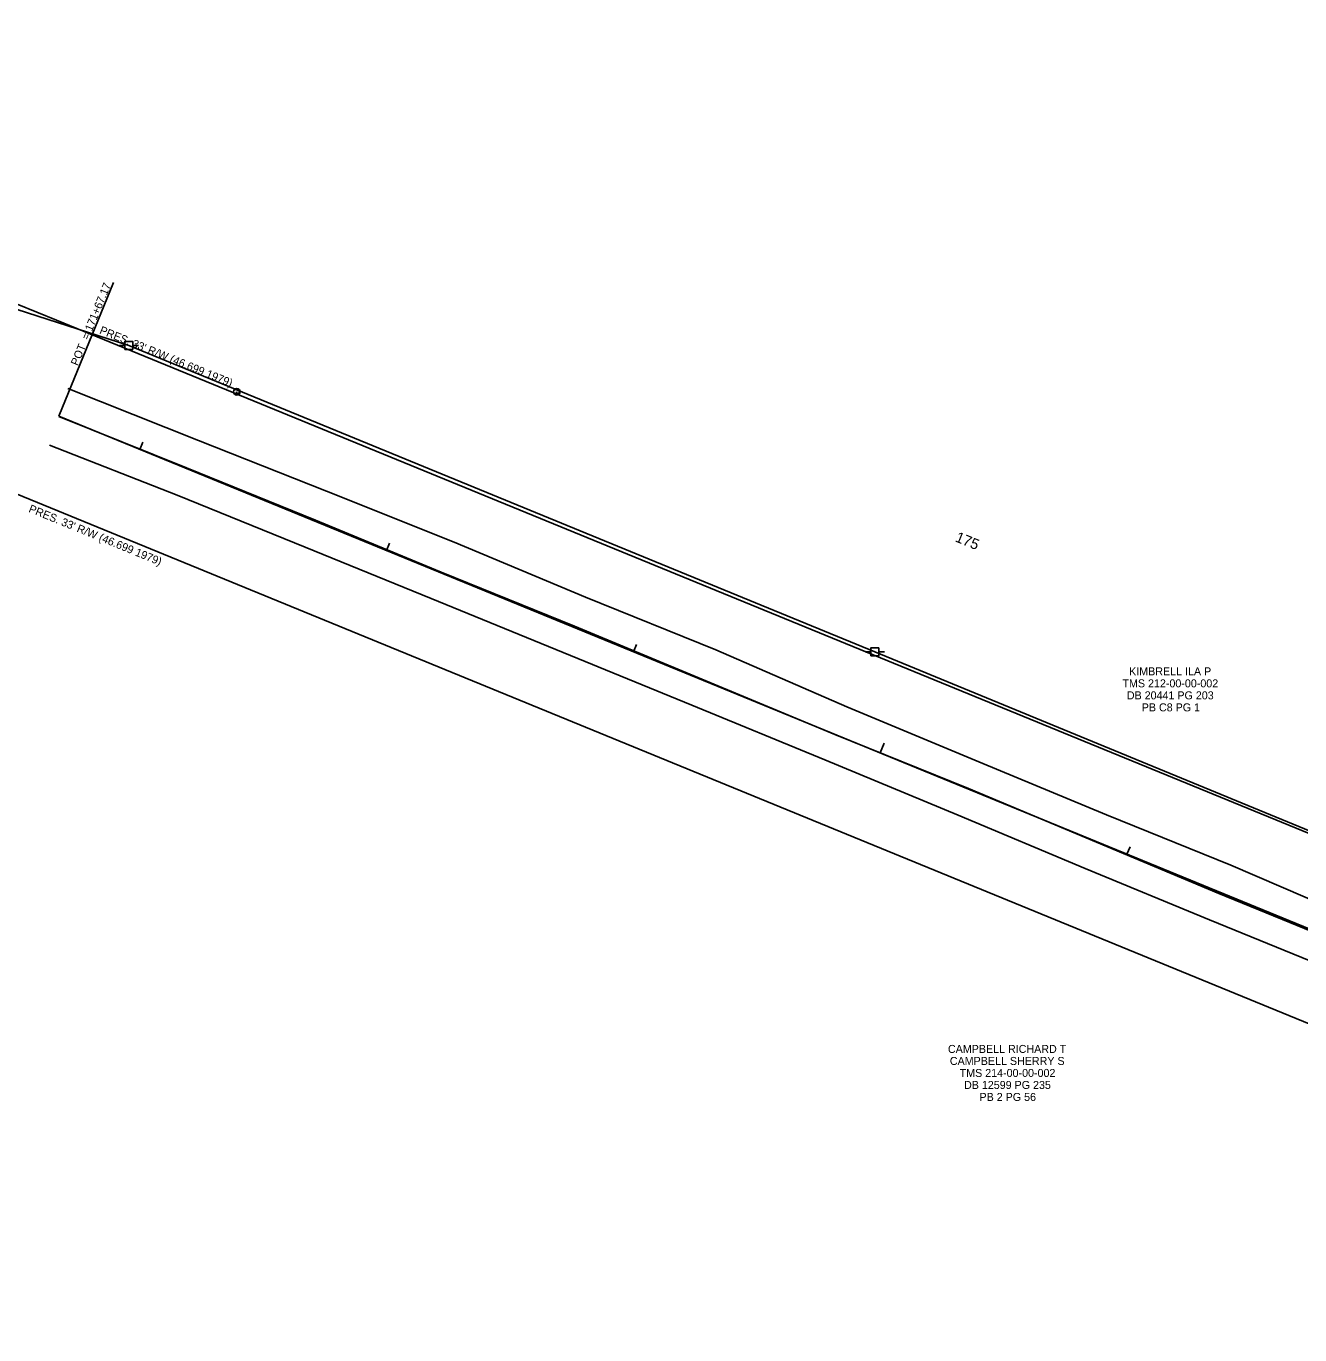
# Model space of a CAD drawing. Extents: x 1903662 to 1907233, y 1108998 to 1112872.
# Drawn here: x 1904852.9 to 1905330.5, y 1110014.7 to 1110505.3 of the extents above; entities that cross this region are included whole.
import ezdxf

# ---------------------------------------------------------------- set-up
doc = ezdxf.new("R2010")
doc.units = 0
for name, color, linetype in [('RD_DTM_BkLn1', 7, 'Continuous'), ('RD_EX_DV_TX_Prop', 7, 'Continuous'), ('RD_EX_Road', 7, 'Continuous'), ('RD_EX_RW', 7, 'Continuous'), ('RD_EX_RW_TX', 7, 'Continuous'), ('RD_EX_UT', 7, 'Continuous'), ('RD_HC_Cl', 7, 'Continuous'), ('RD_HC_Data', 7, 'Continuous'), ('RD_HC_Data_Tic', 7, 'Continuous'), ('RD_HC_TX_Sta20', 7, 'Continuous'), ('SV_UT_Electric_Lines', 7, 'Continuous')]:
    doc.layers.add(name, color=color, linetype=linetype)

msp = doc.modelspace()

# ---------------------------------------------------------------- linework, layer by layer
at = {"layer": 'RD_DTM_BkLn1'}
msp.add_lwpolyline([(1904865.19, 1110359), (1904913.1, 1110339.8), (1904961.42, 1110320.08), (1905008.53, 1110300.58), (1905058.58, 1110280.34), (1905106.3, 1110260.53), (1905156.09, 1110239.84), (1905206.21, 1110219.59), (1905254.3, 1110199.45), (1905300.11, 1110180.14), (1905347.21, 1110160.98), (1905395.33, 1110141.42), (1905443.75, 1110121.81), (1905492.46, 1110101.83), (1905520.15, 1110090.53), (1905547.72, 1110079.36), (1905575.52, 1110068.04), (1905603.32, 1110056.68), (1905630.91, 1110045.24), (1905658.56, 1110033.72), (1905686.41, 1110022.54)], dxfattribs=at)
at = {"layer": 'RD_EX_Road'}
for points in [[(1905496.35, 1110111.49), (1905446.77, 1110132.25), (1905399.76, 1110150.99), (1905351.42, 1110170.63), (1905304.67, 1110190.78), (1905258, 1110209.73), (1905210.14, 1110229.59), (1905160.61, 1110250.11), (1905111.53, 1110271.5), (1905062.64, 1110291.27), (1905013.42, 1110311.88), (1904965.6, 1110330.96), (1904917.58, 1110350.01), (1904868.56, 1110369.54)], [(1905488.55, 1110092.85), (1905440.52, 1110111.68), (1905391.25, 1110131.57), (1905343.49, 1110151.21), (1905296.63, 1110170.35), (1905249.95, 1110189.58), (1905202.45, 1110209.57), (1905152.37, 1110230.29), (1905102.47, 1110250.73), (1905054.27, 1110270.47), (1905004.76, 1110290.72), (1904957.54, 1110310), (1904909.51, 1110329.47), (1904861.73, 1110348.28)]]:
    msp.add_lwpolyline(points, dxfattribs=at)
at = {"layer": 'RD_EX_RW'}
for p, q in [((1904864.32, 1110395.12), (1906497.97, 1109725.51)), ((1904839.26, 1110334.07), (1906209.37, 1109772.47))]:
    msp.add_line(p, q, dxfattribs=at)
msp.add_arc((1904306.14, 1109036.53), 1468.79, 67.6647, 107.11416, dxfattribs=at)
at = {"layer": 'RD_EX_UT'}
for p, q in [((1904887.88, 1110385.61), (1904889.93, 1110385.61)), ((1904891.43, 1110385.65), (1904891.43, 1110385.65)), ((1904892.93, 1110385.61), (1904895.07, 1110385.61)), ((1904931.39, 1110367.72), (1904932.54, 1110367.72)), ((1905167.55, 1110270.72), (1905169.61, 1110270.72)), ((1905171.11, 1110270.76), (1905171.11, 1110270.76)), ((1905172.61, 1110270.72), (1905174.75, 1110270.72))]:
    msp.add_line(p, q, dxfattribs=at)
msp.add_lwpolyline([(1904589.73, 1110482.88), (1904891.43, 1110385.65), (1905171.11, 1110270.76), (1905436.6, 1110161.49), (1905735.85, 1110038.44), (1905992.24, 1109932.67), (1906258.29, 1109823.17), (1906443.47, 1109747.31)], dxfattribs=at)
for points in [[(1904889.93, 1110384.15), (1904889.93, 1110387.15), (1904892.93, 1110387.15), (1904892.93, 1110384.15)], [(1905169.61, 1110269.26), (1905169.61, 1110272.26), (1905172.61, 1110272.26), (1905172.61, 1110269.26)]]:
    msp.add_lwpolyline(points, close=True, dxfattribs=at)
msp.add_circle((1904931.92, 1110368.28), 1.23, dxfattribs=at)
at = {"layer": 'RD_HC_Cl'}
msp.add_line((1904865.19, 1110359.1), (1906221.88, 1109803.01), dxfattribs=at)
at = {"layer": 'RD_HC_Data'}
msp.add_line((1904865.19, 1110359.1), (1904885.74, 1110409.23), dxfattribs=at)
at = {"layer": 'RD_HC_Data_Tic'}
for p, q in [((1904895.57, 1110346.65), (1904896.7, 1110349.43)), ((1904988.09, 1110308.72), (1904989.23, 1110311.5)), ((1905080.62, 1110270.8), (1905081.76, 1110273.57)), ((1905173.15, 1110232.87), (1905174.67, 1110236.57)), ((1905265.68, 1110194.95), (1905266.82, 1110197.72))]:
    msp.add_line(p, q, dxfattribs=at)
at = {"layer": 'SV_UT_Electric_Lines'}
msp.add_lwpolyline([(1904589.73, 1110482.88), (1904891.43, 1110385.65), (1905171.11, 1110270.76), (1905436.6, 1110161.49), (1905735.85, 1110038.44), (1905992.24, 1109932.67), (1906258.29, 1109823.17), (1906443.47, 1109747.31)], dxfattribs=at)

# ---------------------------------------------------------------- texts
at = {"layer": 'RD_EX_DV_TX_Prop'}
for s, p in [('TMS 212-00-00-002', (1905263.99, 1110257.46)), ('KIMBRELL ILA P', (1905266.49, 1110261.96)), ('DB 20441 PG 203', (1905265.63, 1110252.96)), ('PB C8 PG 1', (1905271.22, 1110248.46)), ('CAMPBELL RICHARD T', (1905198.56, 1110120.41)), ('CAMPBELL SHERRY S', (1905199.27, 1110115.91)), ('TMS 214-00-00-002', (1905202.95, 1110111.41)), ('DB 12599 PG 235', (1905204.59, 1110106.91)), ('PB 2 PG 56', (1905210.39, 1110102.41))]:
    msp.add_text(s, height=3, dxfattribs=at).set_placement(p)
at = {"layer": 'RD_EX_RW_TX'}
for p in [(1904880.2, 1110390.23), (1904853.63, 1110323.31)]:
    msp.add_text("PRES. 33' R/W (46.699 1979)", height=3, rotation=337.7118, dxfattribs=at).set_placement(p)
at = {"layer": 'RD_EX_UT'}
msp.add_text('W', height=1.5, dxfattribs=at).set_placement((1904931.3, 1110367.77))
at = {"layer": 'RD_HC_Data'}
msp.add_text('POT  = 171+67.17', height=3, rotation=67.7118, dxfattribs=at).set_placement((1904872.31, 1110377.8))
at = {"layer": 'RD_HC_TX_Sta20'}
msp.add_text('175', height=4, rotation=337.7118, dxfattribs=at).set_placement((1905200.99, 1110312.25))

doc.saveas('drawing.dxf')
